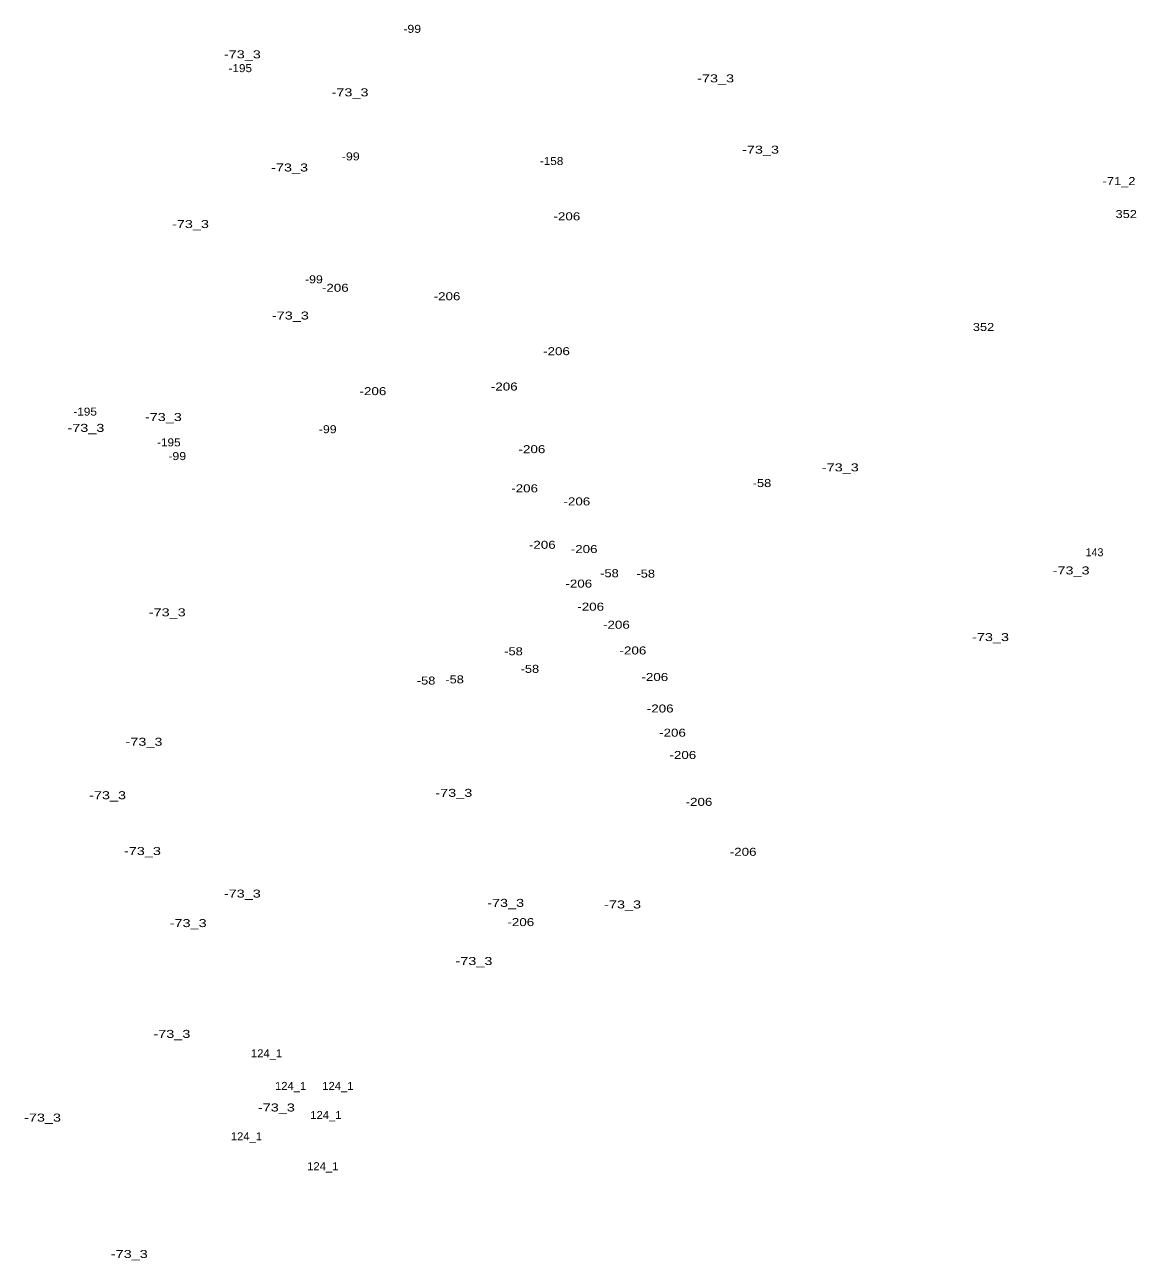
# Model space of a CAD drawing. Extents: x -658110 to -655750, y -1000429 to -997657.
# Drawn here: x -657475 to -656920, y -1000390 to -999772 of the extents above; entities that cross this region are included whole.
import ezdxf
from ezdxf.enums import TextEntityAlignment as Align

# ---------------------------------------------------------------- set-up
doc = ezdxf.new("R2010")
doc.units = 0
doc.header["$LTSCALE"] = 1.6
doc.layers.add('24', color=7, linetype='Continuous')

msp = doc.modelspace()

# ---------------------------------------------------------------- texts
at = {"layer": '24'}
for s, width, p in [('-99', 1.15, (-657281.63, -999776.42)), ('-73_3', 1.35, (-657366.56, -999789.17)), ('-195', 1.1, (-657367.61, -999796.07)), ('-73_3', 1.35, (-657129.93, -999801.18)), ('-73_3', 1.35, (-657312.72, -999808.16)), ('-99', 1.15, (-657312.35, -999840.19)), ('-73_3', 1.35, (-657107.47, -999836.82)), ('-73_3', 1.35, (-657342.93, -999845.74)), ('-158', 1.1, (-657211.951, -999842.5)), ('-71_2', 1.2, (-656928.22, -999852.53)), ('-206', 1.25, (-657204.3, -999870.15)), ('352', 1.2, (-656924.61, -999869.02)), ('-73_3', 1.35, (-657392.5, -999874.02)), ('-99', 1.15, (-657330.78, -999901.65)), ('-206', 1.25, (-657320.08, -999905.87)), ('-206', 1.25, (-657264.21, -999910.1)), ('-73_3', 1.35, (-657342.54, -999919.74)), ('352', 1.2, (-656995.949, -999925.46)), ('-206', 1.25, (-657209.49, -999937.57)), ('-206', 1.25, (-657301.27, -999957.54)), ('-206', 1.25, (-657235.6, -999955.24)), ('-195', 1.1, (-657445.18, -999967.78)), ('-73_3', 1.35, (-657406.05, -999970.49)), ('-73_3', 1.35, (-657444.78, -999975.91)), ('-99', 1.15, (-657323.87, -999976.56)), ('-195', 1.1, (-657403.32, -999983.15)), ('-206', 1.25, (-657221.77, -999986.55)), ('-99', 1.15, (-657399.13, -999990.01)), ('-73_3', 1.35, (-657067.58, -999995.66)), ('-206', 1.25, (-657225.42, -1000006.14)), ('-58', 1.2, (-657106.74, -1000003.5)), ('-206', 1.25, (-657199.3, -1000012.67)), ('-206', 1.25, (-657216.58, -1000034.36)), ('-206', 1.25, (-657195.66, -1000036.48)), ('-58', 1.2, (-657183, -1000048.57)), ('-58', 1.2, (-657164.86, -1000048.76)), ('-73_3', 1.35, (-656952.18, -1000047.18)), ('-206', 1.25, (-657198.34, -1000053.76)), ('-73_3', 1.35, (-657404.12, -1000068.11)), ('-206', 1.25, (-657192.39, -1000065.29)), ('-206', 1.25, (-657179.52, -1000074.31)), ('-73_3', 1.35, (-656992.46, -1000080.49)), ('-58', 1.2, (-657230.98, -1000087.59)), ('-206', 1.25, (-657171.26, -1000087.18)), ('-58', 1.2, (-657222.79, -1000096.37)), ('-58', 1.2, (-657274.68, -1000102.23)), ('-58', 1.2, (-657260.44, -1000101.64)), ('-206', 1.25, (-657160.32, -1000100.44)), ('-206', 1.25, (-657157.63, -1000116.19)), ('-206', 1.25, (-657151.49, -1000128.29)), ('-73_3', 1.35, (-657415.74, -1000132.82)), ('-206', 1.25, (-657146.31, -1000139.43)), ('-73_3', 1.35, (-657433.94, -1000159.54)), ('-73_3', 1.35, (-657260.84, -1000158.36)), ('-206', 1.25, (-657138.24, -1000162.86)), ('-73_3', 1.35, (-657416.51, -1000187.44)), ('-206', 1.25, (-657116.16, -1000187.83)), ('-73_3', 1.35, (-657366.57, -1000208.72)), ('-73_3', 1.35, (-657234.9, -1000213.37)), ('-73_3', 1.35, (-657176.42, -1000214.15)), ('-73_3', 1.35, (-657393.66, -1000223.47)), ('-206', 1.25, (-657227.33, -1000222.98)), ('-73_3', 1.35, (-657250.77, -1000242.43)), ('-73_3', 1.35, (-657401.79, -1000278.86)), ('124_1', 1.05, (-657354.44, -1000288.57)), ('124_1', 1.05, (-657342.42, -1000304.86)), ('124_1', 1.05, (-657318.77, -1000304.86)), ('-73_3', 1.35, (-657349.53, -1000315.65)), ('-73_3', 1.35, (-657466.47, -1000320.7)), ('124_1', 1.05, (-657324.78, -1000319.41)), ('124_1', 1.05, (-657364.52, -1000330.08)), ('124_1', 1.05, (-657326.33, -1000345.01)), ('-73_3', 1.35, (-657423.09, -1000388.88))]:
    msp.add_text(s, height=4, dxfattribs=dict(at, width=width)).set_placement(p, align=Align.CENTER)
msp.add_text('143', height=4, dxfattribs=at).set_placement((-656940.48, -1000038.09), align=Align.CENTER)

doc.saveas('drawing.dxf')
